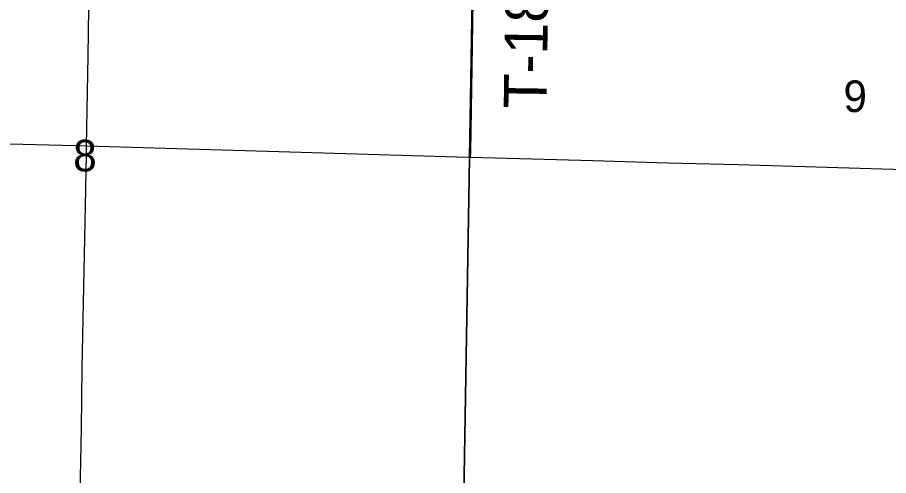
# Model space of a CAD drawing. Extents: x 1587405 to 1714697, y 1028970 to 1155083.
# Drawn here: x 1657777 to 1663879, y 1082271 to 1085481 of the extents above; entities that cross this region are included whole.
import ezdxf

# ---------------------------------------------------------------- set-up
doc = ezdxf.new("R2010")
doc.units = 0
for name, color, linetype in [('GM_X_Section', 7, 'Continuous'), ('GM_X_Section_Text', 7, 'Continuous'), ('GM_X_Township_Road', 7, 'Continuous'), ('GM_X_Township_Road_Text', 7, 'Continuous')]:
    doc.layers.add(name, color=color, linetype=linetype)

msp = doc.modelspace()

# ---------------------------------------------------------------- linework, layer by layer
at = {"layer": 'GM_X_Section'}
for points in [[(1655606.5, 1087308.4), (1660988.4, 1087141.1), (1660898.6, 1081851.1), (1655510.9, 1081994.5)], [(1660988.4, 1087141.1), (1666401.8, 1086987.9), (1666261.8, 1081696.4), (1660898.6, 1081851.1)]]:
    msp.add_lwpolyline(points, close=True, dxfattribs=at)
at = {"layer": 'GM_X_Township_Road'}
for points in [[(1658262, 1084580.6), (1658272.7, 1085210.2), (1658284.6, 1086047), (1658287.8, 1086293.1), (1658292.8, 1086588.4), (1658298.3, 1087031.5), (1658302.5, 1087195.5), (1658310.9, 1087441.5), (1658318.3, 1087654.7), (1658326.9, 1087802.1), (1658340.5, 1087998.6), (1658361.7, 1088441.1), (1658363.2, 1088523.2), (1658364, 1088563.7)], [(1660951.4, 1084501.4), (1660952, 1084538), (1660962.3, 1085128.7), (1660968.1, 1085440.3), (1660974.1, 1085916.2), (1660984.4, 1086489.8), (1660995.6, 1086981.9), (1661012.8, 1087408.3), (1661020.8, 1087588.5), (1661029.3, 1087785.3), (1661047, 1088145.8), (1661063.3, 1088457.2), (1661065.2, 1088489.7)], [(1650681.2, 1084694.5), (1650716.1, 1084694.3), (1651569.6, 1084689), (1652767.7, 1084675.9), (1652964.5, 1084673.5), (1653243.5, 1084669.6), (1654047.7, 1084663), (1654687.9, 1084656.1), (1654983.3, 1084652.1), (1655393.5, 1084646.2), (1655836.6, 1084639.6), (1656246.9, 1084631.4), (1657723.7, 1084595.5), (1658183.1, 1084582.9), (1658262, 1084580.6)], [(1658214.5, 1081928.8), (1658219.9, 1082257.1), (1658226.3, 1082601.6), (1658231.2, 1083028.2), (1658254.6, 1084160.2), (1658260.9, 1084521.2), (1658262, 1084580.6)], [(1658262, 1084580.6), (1659528.5, 1084543.6), (1659922.2, 1084532.7), (1660857.3, 1084504), (1660951.4, 1084501.4)], [(1660951.4, 1084501.4), (1661808.8, 1084477.8), (1662333.8, 1084462.4), (1662826, 1084449.4), (1663990.9, 1084414.4), (1664680.1, 1084395.7), (1665418.5, 1084376.8), (1666271.7, 1084355), (1666333.8, 1084353.1)]]:
    msp.add_lwpolyline(points, dxfattribs=at)

# ---------------------------------------------------------------- texts
at = {"layer": 'GM_X_Section_Text'}
for s, p in [('9', (1663562.8, 1084817.8)), ('8', (1658168.4, 1084402))]:
    msp.add_text(s, height=221, rotation=0.00001, dxfattribs=at).set_placement(p)
at = {"layer": 'GM_X_Township_Road_Text'}
msp.add_text('T-180', height=300, rotation=89.1554, dxfattribs=at).set_placement((1661483, 1084840.6))

doc.saveas('drawing.dxf')
